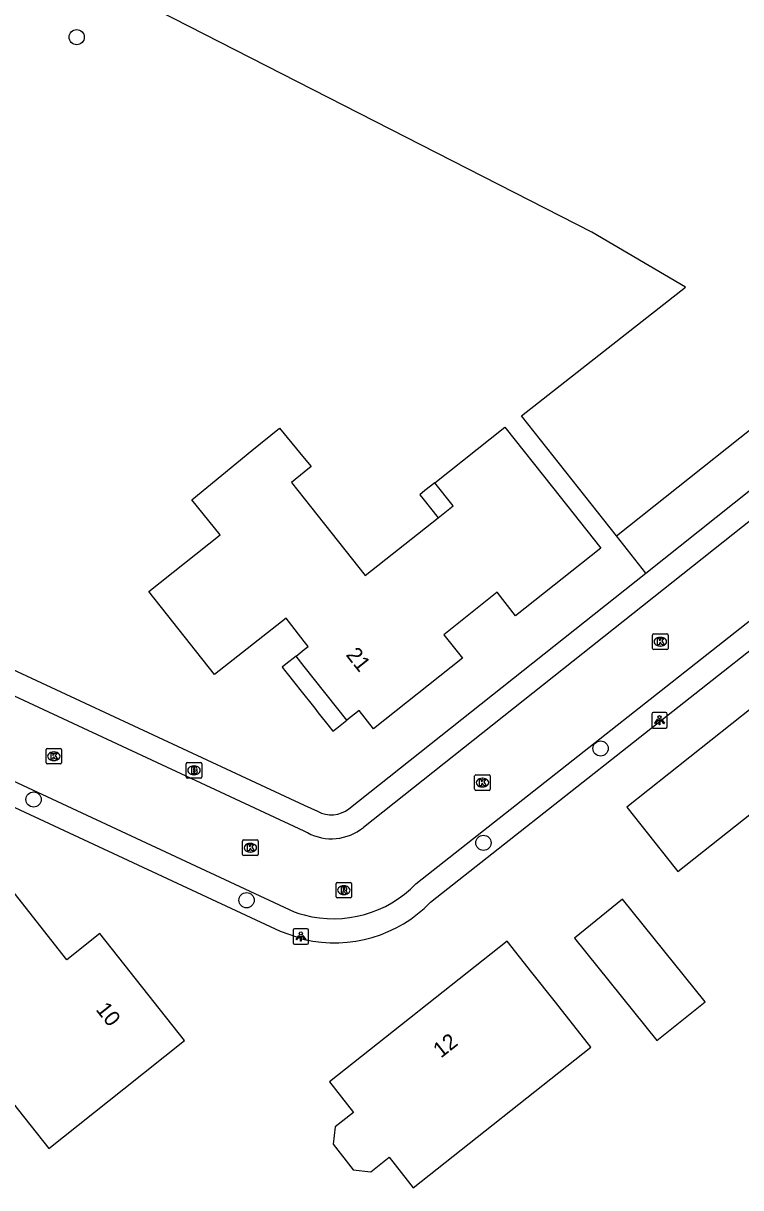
# Model space of a CAD drawing. Extents: x 159628 to 160723, y 388176 to 389416.
# Drawn here: x 159981.9 to 160028.1, y 388671.6 to 388746.5 of the extents above; entities that cross this region are included whole.
import ezdxf

# ---------------------------------------------------------------- set-up
doc = ezdxf.new("R2010")
doc.units = 0
for name, color, linetype in [('IMGEO_Boom', 7, 'Continuous'), ('IMGEO_Brandkraan', 7, 'Continuous'), ('IMGEO_Groenvoorziening', 7, 'Continuous'), ('IMGEO_Kolk', 7, 'Continuous'), ('IMGEO_Lichtpunt', 7, 'Continuous'), ('IMGEO_Loofbos', 7, 'Continuous'), ('IMGEO_Pand', 7, 'Continuous'), ('IMGEO_Pand_nummerreeks', 7, 'Continuous'), ('IMGEO_Pand_overbouw', 7, 'Continuous'), ('IMGEO_Rijbaan_lokaal_open', 7, 'Continuous'), ('IMGEO_Rioolput', 7, 'Continuous'), ('IMGEO_Voetpad_open', 7, 'Continuous')]:
    doc.layers.add(name, color=color, linetype=linetype)

msp = doc.modelspace()

# ---------------------------------------------------------------- linework, layer by layer
at = {"layer": 'IMGEO_Boom'}
for centre in [(159985.351, 388745.609), (160019.069, 388699.844), (159982.578, 388696.562), (160011.528, 388693.773), (159996.284, 388690.079)]:
    msp.add_circle(centre, 0.489, dxfattribs=at)
at = {"layer": 'IMGEO_Brandkraan'}
for p, q in [((159992.4, 388698.01), (159992.4, 388698.862)), ((159992.475, 388698.936), (159993.327, 388698.936)), ((159992.888, 388698.716), (159992.913, 388698.716)), ((159993.401, 388698.862), (159993.401, 388698.01)), ((159993.327, 388697.936), (159992.475, 388697.936)), ((159992.911, 388698.156), (159992.886, 388698.156))]:
    msp.add_line(p, q, dxfattribs=at)
for points in [[(159992.4, 388698.01), (159992.4, 388698.862)], [(159992.475, 388698.936), (159993.327, 388698.936)], [(159992.748, 388698.636), (159992.748, 388698.236), (159992.961, 388698.236)], [(159992.979, 388698.636), (159992.748, 388698.636)], [(159993.401, 388698.862), (159993.401, 388698.01)], [(159993.327, 388697.936), (159992.475, 388697.936)], [(159992.927, 388698.555), (159992.873, 388698.555), (159992.873, 388698.479)], [(159992.873, 388698.479), (159992.926, 388698.479)], [(159992.935, 388698.403), (159992.873, 388698.403), (159992.873, 388698.322)], [(159992.873, 388698.322), (159992.935, 388698.322)]]:
    msp.add_lwpolyline(points, dxfattribs=at)
for centre, radius, start, end in [((159992.477, 388698.86), 0.0765, 91.55205, 178.44795), ((159992.477, 388698.86), 0.0765, 91.55205, 178.44795), ((159992.983, 388698.491), 0.145, 59.4692, 91.53667), ((159993.008, 388698.538), 0.0922, 285.51372, 58.15012), ((159993.325, 388698.86), 0.0765, 1.55205, 88.44795), ((159993.325, 388698.86), 0.0765, 1.55205, 88.44795), ((159992.477, 388698.012), 0.0765, 181.55205, 268.44795), ((159992.477, 388698.012), 0.0765, 181.55205, 268.44795), ((159992.928, 388698.517), 0.0379, 267.82845, 90.93552), ((159992.936, 388698.362), 0.0404, 269.87594, 90.50774), ((159992.967, 388698.487), 0.251, 268.66757, 293.53466), ((159993.013, 388698.346), 0.105, 301.31148, 78.98903), ((159993.325, 388698.012), 0.0765, 271.55205, 358.44795), ((159993.325, 388698.012), 0.0765, 271.55205, 358.44795)]:
    msp.add_arc(centre, radius, start, end, dxfattribs=at)
for centre, major_axis, ratio, start_param, end_param in [((159992.887, 388698.436), (-0.387, 0.002), 0.722429, 4.712389, 7.853982), ((159992.912, 388698.436), (-0.39, 0.002), 0.717154, 1.570796, 4.712389)]:
    msp.add_ellipse(centre, major_axis=major_axis, ratio=ratio, start_param=start_param, end_param=end_param, dxfattribs=at)
at = {"layer": 'IMGEO_Groenvoorziening'}
msp.add_lwpolyline([(160021.986, 388711.129), (160020.086, 388713.523)], dxfattribs=at)
at = {"layer": 'IMGEO_Kolk'}
for p, q in [((160022.412, 388706.285), (160022.412, 388707.137)), ((160022.487, 388707.211), (160023.339, 388707.211)), ((160022.9, 388706.991), (160022.925, 388706.991)), ((160023.413, 388707.137), (160023.413, 388706.285)), ((160023.339, 388706.211), (160022.487, 388706.211)), ((160022.923, 388706.431), (160022.898, 388706.431)), ((159983.38, 388698.919), (159983.38, 388699.771)), ((159983.455, 388699.845), (159984.307, 388699.845)), ((159983.868, 388699.625), (159983.893, 388699.625)), ((159984.381, 388699.771), (159984.381, 388698.919)), ((159984.307, 388698.845), (159983.455, 388698.845)), ((159983.891, 388699.065), (159983.866, 388699.065)), ((160010.964, 388697.222), (160010.964, 388698.074)), ((160011.039, 388698.148), (160011.891, 388698.148)), ((160011.452, 388697.928), (160011.477, 388697.928)), ((160011.965, 388698.074), (160011.965, 388697.222)), ((160011.891, 388697.148), (160011.039, 388697.148)), ((160011.475, 388697.368), (160011.45, 388697.368)), ((159996.032, 388693.03), (159996.032, 388693.882)), ((159996.107, 388693.956), (159996.959, 388693.956)), ((159996.52, 388693.736), (159996.545, 388693.736)), ((159997.033, 388693.882), (159997.033, 388693.03)), ((159996.959, 388692.956), (159996.107, 388692.956)), ((159996.543, 388693.176), (159996.518, 388693.176))]:
    msp.add_line(p, q, dxfattribs=at)
for points in [[(160022.412, 388706.285), (160022.412, 388707.137)], [(160022.487, 388707.211), (160023.339, 388707.211)], [(160022.733, 388706.911), (160022.856, 388706.911), (160022.856, 388706.76), (160022.986, 388706.911), (160023.15, 388706.911), (160023.004, 388706.76), (160023.157, 388706.511), (160023.005, 388706.511), (160022.92, 388706.675), (160022.856, 388706.608), (160022.856, 388706.511), (160022.733, 388706.511), (160022.733, 388706.911)], [(160023.413, 388707.137), (160023.413, 388706.285)], [(160023.339, 388706.211), (160022.487, 388706.211)], [(159983.38, 388698.919), (159983.38, 388699.771)], [(159983.455, 388699.845), (159984.307, 388699.845)], [(159983.701, 388699.545), (159983.824, 388699.545), (159983.824, 388699.394), (159983.954, 388699.545), (159984.118, 388699.545), (159983.972, 388699.394), (159984.125, 388699.145), (159983.973, 388699.145), (159983.888, 388699.309), (159983.824, 388699.242), (159983.824, 388699.145), (159983.701, 388699.145), (159983.701, 388699.545)], [(159984.381, 388699.771), (159984.381, 388698.919)], [(159984.307, 388698.845), (159983.455, 388698.845)], [(160010.964, 388697.222), (160010.964, 388698.074)], [(160011.039, 388698.148), (160011.891, 388698.148)], [(160011.285, 388697.848), (160011.408, 388697.848), (160011.408, 388697.697), (160011.538, 388697.848), (160011.702, 388697.848), (160011.556, 388697.697), (160011.709, 388697.448), (160011.557, 388697.448), (160011.472, 388697.612), (160011.408, 388697.545), (160011.408, 388697.448), (160011.285, 388697.448), (160011.285, 388697.848)], [(160011.965, 388698.074), (160011.965, 388697.222)], [(160011.891, 388697.148), (160011.039, 388697.148)], [(159996.032, 388693.03), (159996.032, 388693.882)], [(159996.107, 388693.956), (159996.959, 388693.956)], [(159996.353, 388693.656), (159996.476, 388693.656), (159996.476, 388693.505), (159996.606, 388693.656), (159996.77, 388693.656), (159996.624, 388693.505), (159996.777, 388693.256), (159996.625, 388693.256), (159996.54, 388693.42), (159996.476, 388693.353), (159996.476, 388693.256), (159996.353, 388693.256), (159996.353, 388693.656)], [(159997.033, 388693.882), (159997.033, 388693.03)], [(159996.959, 388692.956), (159996.107, 388692.956)]]:
    msp.add_lwpolyline(points, dxfattribs=at)
for centre, start, end in [((160022.489, 388707.135), 91.55205, 178.44795), ((160022.489, 388707.135), 91.55205, 178.44795), ((160023.337, 388707.135), 1.55205, 88.44795), ((160023.337, 388707.135), 1.55205, 88.44795), ((160022.489, 388706.287), 181.55205, 268.44795), ((160022.489, 388706.287), 181.55205, 268.44795), ((160023.337, 388706.287), 271.55205, 358.44795), ((160023.337, 388706.287), 271.55205, 358.44795), ((159983.457, 388699.769), 91.55205, 178.44795), ((159983.457, 388699.769), 91.55205, 178.44795), ((159984.305, 388699.769), 1.55205, 88.44795), ((159984.305, 388699.769), 1.55205, 88.44795), ((159983.457, 388698.921), 181.55205, 268.44795), ((159983.457, 388698.921), 181.55205, 268.44795), ((159984.305, 388698.921), 271.55205, 358.44795), ((159984.305, 388698.921), 271.55205, 358.44795), ((160011.041, 388698.072), 91.55205, 178.44795), ((160011.041, 388698.072), 91.55205, 178.44795), ((160011.889, 388698.072), 1.55205, 88.44795), ((160011.889, 388698.072), 1.55205, 88.44795), ((160011.041, 388697.224), 181.55205, 268.44795), ((160011.041, 388697.224), 181.55205, 268.44795), ((160011.889, 388697.224), 271.55205, 358.44795), ((160011.889, 388697.224), 271.55205, 358.44795), ((159996.109, 388693.88), 91.55205, 178.44795), ((159996.109, 388693.88), 91.55205, 178.44795), ((159996.957, 388693.88), 1.55205, 88.44795), ((159996.957, 388693.88), 1.55205, 88.44795), ((159996.109, 388693.032), 181.55205, 268.44795), ((159996.109, 388693.032), 181.55205, 268.44795), ((159996.957, 388693.032), 271.55205, 358.44795), ((159996.957, 388693.032), 271.55205, 358.44795)]:
    msp.add_arc(centre, 0.0765, start, end, dxfattribs=at)
for centre, major_axis, ratio, start_param, end_param in [((160022.899, 388706.711), (-0.387, 0.002), 0.722429, 4.712389, 7.853982), ((160022.924, 388706.711), (-0.39, 0.002), 0.717154, 1.570796, 4.712389), ((159983.867, 388699.345), (-0.387, 0.002), 0.722429, 4.712389, 7.853982), ((159983.892, 388699.345), (-0.39, 0.002), 0.717154, 1.570796, 4.712389), ((160011.451, 388697.648), (-0.387, 0.002), 0.722429, 4.712389, 7.853982), ((160011.476, 388697.648), (-0.39, 0.002), 0.717154, 1.570796, 4.712389), ((159996.519, 388693.456), (-0.387, 0.002), 0.722429, 4.712389, 7.853982), ((159996.544, 388693.456), (-0.39, 0.002), 0.717154, 1.570796, 4.712389)]:
    msp.add_ellipse(centre, major_axis=major_axis, ratio=ratio, start_param=start_param, end_param=end_param, dxfattribs=at)
at = {"layer": 'IMGEO_Lichtpunt'}
for p, q in [((160022.363, 388702.061), (160022.363, 388701.254)), ((160022.363, 388702.061), (160022.363, 388701.254)), ((160023.265, 388702.156), (160022.457, 388702.156)), ((160023.265, 388702.156), (160022.457, 388702.156)), ((160023.359, 388701.254), (160023.359, 388702.061)), ((160023.359, 388701.254), (160023.359, 388702.061)), ((160022.457, 388701.16), (160023.265, 388701.16)), ((160022.457, 388701.16), (160023.265, 388701.16)), ((159999.279, 388688.148), (159999.279, 388687.341)), ((159999.279, 388688.148), (159999.279, 388687.341)), ((160000.181, 388688.243), (159999.373, 388688.243)), ((160000.181, 388688.243), (159999.373, 388688.243)), ((160000.275, 388687.341), (160000.275, 388688.148)), ((160000.275, 388687.341), (160000.275, 388688.148)), ((159999.373, 388687.247), (160000.181, 388687.247)), ((159999.373, 388687.247), (160000.181, 388687.247))]:
    msp.add_line(p, q, dxfattribs=at)
for points in [[(160022.737, 388701.725), (160022.776, 388701.697), (160022.588, 388701.435), (160022.55, 388701.462), (160022.737, 388701.725)], [(160022.839, 388701.677), (160022.886, 388701.677), (160022.886, 388701.355), (160022.839, 388701.355), (160022.839, 388701.677)], [(160022.949, 388701.697), (160022.987, 388701.724), (160023.174, 388701.462), (160023.135, 388701.434), (160022.949, 388701.697)], [(159999.653, 388687.812), (159999.692, 388687.784), (159999.504, 388687.522), (159999.466, 388687.549), (159999.653, 388687.812)], [(159999.755, 388687.764), (159999.802, 388687.764), (159999.802, 388687.442), (159999.755, 388687.442), (159999.755, 388687.764)], [(159999.865, 388687.784), (159999.903, 388687.811), (160000.09, 388687.549), (160000.051, 388687.521), (159999.865, 388687.784)]]:
    msp.add_lwpolyline(points, dxfattribs=at)
for centre in [(160022.862, 388701.859), (159999.778, 388687.946)]:
    msp.add_circle(centre, 0.0994, dxfattribs=at)
for centre, start, end in [((160022.457, 388702.061), 90, 180), ((160022.457, 388702.061), 90, 180), ((160023.265, 388702.061), 0, 90), ((160023.265, 388702.061), 0, 90), ((160022.457, 388701.254), 180, 270), ((160022.457, 388701.254), 180, 270), ((160023.265, 388701.254), 270, 0), ((160023.265, 388701.254), 270, 360), ((159999.373, 388688.148), 90, 180), ((159999.373, 388688.148), 90, 180), ((160000.181, 388688.148), 0, 90), ((160000.181, 388688.148), 0, 90), ((159999.373, 388687.341), 180, 270), ((159999.373, 388687.341), 180, 270), ((160000.181, 388687.341), 270, 0), ((160000.181, 388687.341), 270, 360)]:
    msp.add_arc(centre, 0.0946, start, end, dxfattribs=at)
at = {"layer": 'IMGEO_Loofbos'}
for points in [[(160020.086, 388713.523), (160013.968, 388721.234), (160024.53, 388729.529), (160018.506, 388733.064), (159966.614, 388759.565)], [(160020.086, 388713.523), (160032.727, 388723.555)]]:
    msp.add_lwpolyline(points, dxfattribs=at)
at = {"layer": 'IMGEO_Pand'}
for points in [[(159989.984, 388709.951), (159994.588, 388713.594), (159992.753, 388715.847), (159996.63, 388719.005), (159998.414, 388720.458), (160000, 388718.511), (160000.435, 388717.977), (160000, 388717.623), (159999.178, 388716.953), (160000, 388715.916), (160003.923, 388710.968), (160008.611, 388714.685), (160009.572, 388715.447), (160008.391, 388716.935), (160012.912, 388720.52), (160015.982, 388716.649), (160019.088, 388712.731), (160013.603, 388708.377), (160012.404, 388709.889), (160008.972, 388707.157), (160010.171, 388705.645), (160004.453, 388701.116), (160003.526, 388702.292), (160002.743, 388701.67), (160000, 388705.122), (159999.472, 388705.787), (160000, 388706.206), (160000.255, 388706.409), (160000, 388706.735), (159998.828, 388708.235), (159994.225, 388704.592), (159989.984, 388709.951)], [(160035.133, 388702.915), (160032.913, 388705.71), (160020.759, 388696.061), (160023.863, 388692.141), (160024.03, 388691.93), (160029.913, 388696.589), (160034.199, 388691.176), (160037.824, 388694.061), (160041.735, 388697.175), (160037.63, 388702.344), (160036.378, 388701.349), (160035.133, 388702.915)], [(159988.379, 388677.941), (159992.295, 388681.048), (159986.848, 388687.94), (159984.721, 388686.251), (159981.322, 388690.566), (159977.4, 388687.465), (159975.37, 388685.86), (159978.794, 388681.56), (159978.09, 388681), (159983.55, 388674.11), (159988.379, 388677.941)], [(160017.38, 388687.639), (160022.682, 388681.045), (160025.793, 388683.546), (160020.489, 388690.139), (160017.38, 388687.639)], [(160018.447, 388680.634), (160016.163, 388683.519), (160014.643, 388685.438), (160013.059, 388687.439), (160001.615, 388678.398), (160003.17, 388676.428), (160001.994, 388675.496), (160001.857, 388674.381), (160003.151, 388672.73), (160004.275, 388672.599), (160005.466, 388673.542), (160007.017, 388671.584), (160018.447, 388680.634)]]:
    msp.add_lwpolyline(points, dxfattribs=at)
at = {"layer": 'IMGEO_Pand_overbouw'}
for points in [[(160008.391, 388716.935), (160007.765, 388716.438), (160007.428, 388716.171), (160007.627, 388715.921), (160008.611, 388714.685), (160009.572, 388715.447)], [(160002.743, 388701.67), (160000, 388705.122), (159999.472, 388705.787), (159998.822, 388705.271), (159998.571, 388705.071), (159998.802, 388704.782), (159999.474, 388703.936), (159999.704, 388703.647), (160000.668, 388702.433), (160000.898, 388702.143), (160001.607, 388701.251), (160001.842, 388700.955), (160002.093, 388701.155)]]:
    msp.add_lwpolyline(points, close=True, dxfattribs=at)
at = {"layer": 'IMGEO_Rijbaan_lokaal_open'}
for points in [[(160030.797, 388716.171), (160003.805, 388694.767)], [(160007.188, 388691.137), (160033.807, 388712.113)], [(160000.211, 388694.426), (160000, 388694.524), (159965.493, 388710.595)], [(159963.395, 388706.091), (159999.352, 388689.335), (159999.646, 388689.235), (160000, 388689.132)]]:
    msp.add_lwpolyline(points, dxfattribs=at)
for centre, radius, start, end in [((160001.754, 388697.278), 3.242, 241.58829, 309.25175), ((160001.879, 388696.281), 7.392, 255.27041, 315.9011)]:
    msp.add_arc(centre, radius, start, end, dxfattribs=at)
at = {"layer": 'IMGEO_Rioolput'}
for p, q in [((160002.043, 388690.302), (160002.043, 388691.154)), ((160002.118, 388691.228), (160002.97, 388691.228)), ((160003.044, 388691.154), (160003.044, 388690.302)), ((160002.554, 388690.448), (160002.529, 388690.448)), ((160002.531, 388691.008), (160002.556, 388691.008)), ((160002.97, 388690.228), (160002.118, 388690.228))]:
    msp.add_line(p, q, dxfattribs=at)
for points in [[(160002.043, 388690.302), (160002.043, 388691.154)], [(160002.118, 388691.228), (160002.97, 388691.228)], [(160003.044, 388691.154), (160003.044, 388690.302)], [(160002.632, 388690.926), (160002.38, 388690.928), (160002.38, 388690.528)], [(160002.38, 388690.528), (160002.504, 388690.528), (160002.504, 388690.69), (160002.515, 388690.69)], [(160002.558, 388690.847), (160002.504, 388690.847), (160002.504, 388690.766)], [(160002.504, 388690.766), (160002.556, 388690.766)], [(160002.562, 388690.661), (160002.633, 388690.528), (160002.773, 388690.528), (160002.708, 388690.654)], [(160002.97, 388690.228), (160002.118, 388690.228)]]:
    msp.add_lwpolyline(points, dxfattribs=at)
for centre, radius, start, end in [((160002.12, 388691.152), 0.0765, 91.55205, 178.44795), ((160002.12, 388691.152), 0.0765, 91.55205, 178.44795), ((160002.968, 388691.152), 0.0765, 1.55205, 88.44795), ((160002.968, 388691.152), 0.0765, 1.55205, 88.44795), ((160002.514, 388690.637), 0.0533, 26.02933, 88.69889), ((160002.54, 388690.955), 0.19, 274.7715, 282.96867), ((160002.564, 388690.751), 0.0964, 77.00612, 93.18647), ((160002.578, 388690.808), 0.0378, 276.66336, 79.67722), ((160002.631, 388690.816), 0.109, 350.36119, 89.41601), ((160002.629, 388690.816), 0.112, 277.58423, 350.98172), ((160002.613, 388690.601), 0.108, 29.51342, 73.79051), ((160002.12, 388690.304), 0.0765, 181.55205, 268.44795), ((160002.12, 388690.304), 0.0765, 181.55205, 268.44795), ((160002.968, 388690.304), 0.0765, 271.55205, 358.44795), ((160002.968, 388690.304), 0.0765, 271.55205, 358.44795)]:
    msp.add_arc(centre, radius, start, end, dxfattribs=at)
for centre, major_axis, ratio, start_param, end_param in [((160002.53, 388690.728), (-0.387, 0.002), 0.722429, 4.712389, 7.853982), ((160002.555, 388690.728), (-0.39, 0.002), 0.717154, 1.570796, 4.712389)]:
    msp.add_ellipse(centre, major_axis=major_axis, ratio=ratio, start_param=start_param, end_param=end_param, dxfattribs=at)
at = {"layer": 'IMGEO_Voetpad_open'}
for points in [[(159937.328, 388725.355), (160000, 388696.201), (160000.854, 388695.804)], [(159935.176, 388717.566), (159998.439, 388688.089), (160000, 388687.563)], [(160021.986, 388711.129), (160029.882, 388717.395)], [(160002.873, 388695.961), (160021.986, 388711.129)], [(160008.129, 388689.947), (160034.25, 388710.535)]]:
    msp.add_lwpolyline(points, dxfattribs=at)
for centre, radius, start, end in [((160001.744, 388697.422), 1.846, 241.18815, 307.70473), ((160001.955, 388695.947), 8.609, 256.87377, 315.816)]:
    msp.add_arc(centre, radius, start, end, dxfattribs=at)

# ---------------------------------------------------------------- texts
at = {"layer": 'IMGEO_Pand_nummerreeks'}
for s, rotation, p in [('21', 308.46751, (160002.637, 388705.855)), ('10', 308.32061, (159986.543, 388683.035)), ('12', 38.30947, (160008.791, 388679.887))]:
    msp.add_text(s, height=1, rotation=rotation, dxfattribs=at).set_placement(p)

doc.saveas('drawing.dxf')
